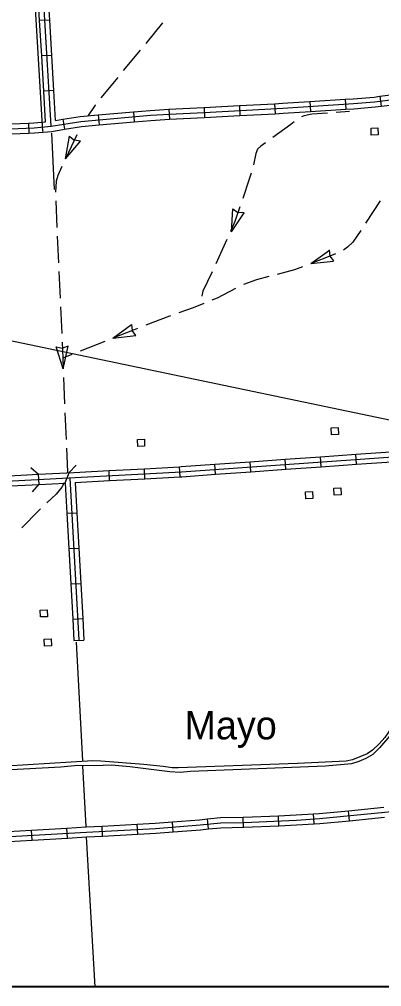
# Model space of a CAD drawing. Extents: x -0.3 to 2.65, y 0 to 1.9.
# Drawn here: x 0.8796 to 0.9445, y 0.1443 to 0.3171 of the extents above; entities that cross this region are included whole.
import ezdxf

# ---------------------------------------------------------------- set-up
doc = ezdxf.new("R2010")
doc.units = 0
for name, color, linetype in [('Default', 7, 'Continuous'), ('DSN_DRFT_DNC', 7, 'Continuous'), ('Level 11', 7, 'Continuous'), ('Level 12', 7, 'Continuous'), ('Level 14', 7, 'Continuous'), ('Level 15', 7, 'Continuous'), ('Level 19', 7, 'Continuous'), ('Level 29', 7, 'Continuous'), ('Level 6', 7, 'Continuous')]:
    doc.layers.add(name, color=color, linetype=linetype)

msp = doc.modelspace()

# ---------------------------------------------------------------- linework, layer by layer
at = {"layer": 'Default'}
msp.add_lwpolyline([(0.97177, 0.24009), (0.73293, 0.28998), (0.80083, 0.28386)], dxfattribs=at)
at = {"layer": 'DSN_DRFT_DNC'}
msp.add_lwpolyline([(0.38477, 0.54167), (1.0319, 0.54167), (1.0319, 0.1443), (0.38477, 0.1443)], close=True, dxfattribs=at)
at = {"layer": 'Level 11'}
msp.add_line((0.89162, 0.17102), (0.89316, 0.14427), dxfattribs=at)
for points in [[(0.8854, 0.29676), (0.88588, 0.2867)], [(0.88983, 0.20585), (0.89092, 0.18462)], [(0.89097, 0.18371), (0.89152, 0.17288)]]:
    msp.add_lwpolyline(points, dxfattribs=at)
at = {"layer": 'Level 12'}
for p, q in [((0.88791, 0.29222), (0.88864, 0.29627)), ((0.88864, 0.29627), (0.88948, 0.29556)), ((0.88791, 0.29222), (0.89056, 0.29536)), ((0.89056, 0.29536), (0.88949, 0.29555)), ((0.91758, 0.27914), (0.91784, 0.28324)), ((0.91758, 0.27914), (0.91986, 0.28256)), ((0.91784, 0.28324), (0.91875, 0.28263)), ((0.91986, 0.28256), (0.91876, 0.28263)), ((0.93178, 0.27348), (0.93511, 0.27588)), ((0.93507, 0.27591), (0.93521, 0.27482)), ((0.93178, 0.27348), (0.93587, 0.2739)), ((0.93588, 0.27395), (0.93522, 0.27481)), ((0.89638, 0.26015), (0.89968, 0.2626)), ((0.89968, 0.2626), (0.8998, 0.26152)), ((0.90046, 0.26063), (0.89981, 0.2615)), ((0.89638, 0.26015), (0.90046, 0.26063)), ((0.88626, 0.25862), (0.88733, 0.25838)), ((0.8875, 0.2547), (0.88626, 0.25862)), ((0.88838, 0.25871), (0.88734, 0.25838)), ((0.8875, 0.2547), (0.88838, 0.25871))]:
    msp.add_line(p, q, dxfattribs=at)
for points in [[(0.90528, 0.31649), (0.90226, 0.31283)], [(0.90126, 0.31161), (0.89824, 0.30796)], [(0.89724, 0.30674), (0.89422, 0.30308)], [(0.89322, 0.30186), (0.89318, 0.30181), (0.89196, 0.29992), (0.89194, 0.2999)], [(0.93475, 0.30038), (0.93194, 0.3002), (0.93059, 0.29989), (0.93009, 0.29968)], [(0.93869, 0.30063), (0.93632, 0.30048)], [(0.9288, 0.29879), (0.92823, 0.29831), (0.92498, 0.29599)], [(0.88993, 0.29651), (0.88791, 0.29222)], [(0.9237, 0.29508), (0.92283, 0.29445), (0.92223, 0.2939), (0.92194, 0.29312), (0.92152, 0.29114)], [(0.88724, 0.2908), (0.88651, 0.28924), (0.88624, 0.28821), (0.88611, 0.28626)], [(0.92109, 0.28962), (0.92076, 0.28858), (0.9196, 0.28513)], [(0.88615, 0.28468), (0.88637, 0.27995)], [(0.91909, 0.28363), (0.91821, 0.28101), (0.91742, 0.2792)], [(0.94417, 0.28468), (0.94158, 0.28072)], [(0.88644, 0.27837), (0.88665, 0.27364)], [(0.94071, 0.27939), (0.93932, 0.27728), (0.93837, 0.27639), (0.93762, 0.27589)], [(0.91678, 0.27776), (0.91477, 0.27346)], [(0.93619, 0.27522), (0.93427, 0.27442), (0.93178, 0.27348)], [(0.88672, 0.27206), (0.88693, 0.26732)], [(0.91411, 0.27203), (0.91247, 0.26852), (0.91227, 0.26774), (0.91227, 0.26768)], [(0.93031, 0.27292), (0.92884, 0.27236), (0.92578, 0.27155)], [(0.92425, 0.27115), (0.92207, 0.27057), (0.91972, 0.26976)], [(0.91832, 0.26903), (0.91505, 0.26731), (0.91409, 0.26692)], [(0.91262, 0.26632), (0.91071, 0.26555), (0.90818, 0.26467)], [(0.887, 0.26575), (0.88722, 0.26101)], [(0.90669, 0.26415), (0.90648, 0.26407), (0.90226, 0.26246)], [(0.90079, 0.26189), (0.90021, 0.26167), (0.89638, 0.26015)], [(0.88729, 0.25943), (0.88741, 0.25659), (0.88749, 0.2547)], [(0.89491, 0.25957), (0.89051, 0.25782)], [(0.88904, 0.25723), (0.88741, 0.25659)], [(0.88755, 0.25312), (0.88774, 0.24839)], [(0.88781, 0.24681), (0.888, 0.24207)], [(0.88806, 0.2405), (0.88823, 0.23628), (0.88821, 0.23616)], [(0.88766, 0.23428), (0.88722, 0.23351), (0.88624, 0.23226), (0.88459, 0.23071)], [(0.88344, 0.22963), (0.88306, 0.22928), (0.88009, 0.22628)]]:
    msp.add_lwpolyline(points, dxfattribs=at)
at = {"layer": 'Level 14'}
for points in [[(0.95175, 0.1989), (0.94972, 0.19527), (0.94627, 0.18952), (0.94407, 0.18692), (0.94286, 0.18578), (0.94164, 0.18505), (0.9404, 0.18451), (0.93905, 0.18411), (0.93442, 0.18368), (0.91024, 0.1827), (0.90842, 0.18252), (0.90657, 0.18267), (0.89938, 0.18355), (0.89614, 0.18384), (0.89313, 0.18374), (0.89009, 0.18382), (0.88704, 0.18352), (0.88038, 0.18311), (0.86671, 0.18245)], [(0.95178, 0.20043), (0.94566, 0.18973), (0.94505, 0.18881), (0.94403, 0.18769), (0.94284, 0.18652), (0.94185, 0.18585), (0.93925, 0.18483), (0.93808, 0.18458), (0.92938, 0.18416), (0.90804, 0.18335), (0.90699, 0.18339), (0.90537, 0.18363), (0.90194, 0.184), (0.89425, 0.18457), (0.8928, 0.18464), (0.87338, 0.18344)]]:
    msp.add_lwpolyline(points, dxfattribs=at)
at = {"layer": 'Level 15'}
for p, q in [((0.88507, 0.31699), (0.88328, 0.31689)), ((0.88545, 0.31069), (0.88365, 0.31058)), ((0.88582, 0.30438), (0.88403, 0.30427)), ((0.93791, 0.30284), (0.93803, 0.30105)), ((0.94415, 0.30338), (0.94438, 0.3016)), ((0.90638, 0.30105), (0.90648, 0.29926)), ((0.91269, 0.30135), (0.91279, 0.29956)), ((0.919, 0.3017), (0.9191, 0.29991)), ((0.92531, 0.30205), (0.92541, 0.30025)), ((0.93161, 0.30244), (0.93172, 0.30065)), ((0.88743, 0.29926), (0.88771, 0.29749)), ((0.89376, 0.30005), (0.89391, 0.29826)), ((0.90005, 0.30059), (0.90021, 0.2988)), ((0.88126, 0.29858), (0.88133, 0.29679)), ((0.93364, 0.23717), (0.93351, 0.23896)), ((0.93994, 0.23762), (0.93982, 0.23941)), ((0.90211, 0.23504), (0.90201, 0.23683)), ((0.90842, 0.23538), (0.90832, 0.23717)), ((0.91473, 0.23583), (0.91461, 0.23762)), ((0.92104, 0.23628), (0.92091, 0.23807)), ((0.92734, 0.23672), (0.92721, 0.23851)), ((0.88318, 0.23403), (0.88308, 0.23582)), ((0.88783, 0.23428), (0.88856, 0.23611)), ((0.8958, 0.2347), (0.8957, 0.2365)), ((0.88813, 0.22886), (0.88992, 0.22896)), ((0.88849, 0.22255), (0.89028, 0.22265)), ((0.88884, 0.21624), (0.89064, 0.21634)), ((0.8892, 0.20993), (0.89099, 0.21003)), ((0.88942, 0.20611), (0.89121, 0.20621)), ((0.92606, 0.17303), (0.92598, 0.17482)), ((0.93238, 0.17336), (0.93227, 0.17515)), ((0.9387, 0.17393), (0.93853, 0.17572)), ((0.89454, 0.17117), (0.89444, 0.17296)), ((0.90085, 0.17151), (0.90075, 0.1733)), ((0.90718, 0.17192), (0.90703, 0.17371)), ((0.91349, 0.17246), (0.91331, 0.17425)), ((0.91972, 0.17275), (0.91969, 0.17454)), ((0.88193, 0.17047), (0.88182, 0.17226)), ((0.88823, 0.17082), (0.88813, 0.17262))]:
    msp.add_line(p, q, dxfattribs=at)
for points in [[(0.88531, 0.29802), (0.88159, 0.36102), (0.88161, 0.36181), (0.88173, 0.36213), (0.88187, 0.36229), (0.8827, 0.36244), (0.91142, 0.36457), (0.92837, 0.36552), (0.92864, 0.36569), (0.92884, 0.36597), (0.92889, 0.36641), (0.92854, 0.37227)], [(0.88383, 0.29711), (0.88011, 0.36011), (0.88014, 0.3609), (0.88025, 0.36122), (0.88039, 0.36138), (0.88122, 0.36153), (0.90995, 0.36366), (0.92689, 0.36462), (0.92716, 0.36478), (0.92736, 0.36506), (0.92742, 0.3655), (0.92707, 0.37136)], [(0.88507, 0.31699), (0.8847, 0.3233)], [(0.88328, 0.31689), (0.88291, 0.32319)], [(0.88365, 0.31058), (0.88328, 0.31689)], [(0.88545, 0.31069), (0.88507, 0.31699)], [(0.88403, 0.30427), (0.88365, 0.31058)], [(0.88582, 0.30438), (0.88545, 0.31069)], [(0.88435, 0.29882), (0.88403, 0.30427)], [(0.88613, 0.29905), (0.88582, 0.30438)], [(0.82448, 0.29532), (0.86117, 0.29696), (0.86927, 0.29721), (0.88227, 0.29774), (0.88531, 0.29802), (0.89065, 0.29889), (0.9031, 0.29997), (0.90771, 0.30025), (0.91272, 0.30047), (0.92678, 0.30125), (0.9394, 0.30206), (0.94318, 0.30237), (0.94835, 0.30302)], [(0.93161, 0.30244), (0.93791, 0.30284)], [(0.93791, 0.30284), (0.93934, 0.30293), (0.94309, 0.30324), (0.94415, 0.30338)], [(0.94415, 0.30338), (0.94741, 0.30379)], [(0.90005, 0.30059), (0.90304, 0.30085), (0.90638, 0.30105)], [(0.90638, 0.30105), (0.90766, 0.30113), (0.91267, 0.30135), (0.91269, 0.30135)], [(0.91269, 0.30135), (0.919, 0.3017)], [(0.919, 0.3017), (0.92531, 0.30205)], [(0.92531, 0.30205), (0.92673, 0.30213), (0.93161, 0.30244)], [(0.93172, 0.30065), (0.93803, 0.30105)], [(0.93803, 0.30105), (0.93947, 0.30114), (0.94328, 0.30146), (0.94438, 0.3016)], [(0.94438, 0.3016), (0.9475, 0.30199)], [(0.88613, 0.29905), (0.88743, 0.29926)], [(0.88743, 0.29926), (0.89054, 0.29977), (0.89376, 0.30005)], [(0.89376, 0.30005), (0.90005, 0.30059)], [(0.90021, 0.2988), (0.90317, 0.29906), (0.90648, 0.29926)], [(0.90648, 0.29926), (0.90776, 0.29933), (0.91276, 0.29956), (0.91279, 0.29956)], [(0.91279, 0.29956), (0.9191, 0.29991)], [(0.9191, 0.29991), (0.92541, 0.30025)], [(0.92541, 0.30025), (0.92684, 0.30033), (0.93172, 0.30065)], [(0.87494, 0.29833), (0.88126, 0.29858)], [(0.88126, 0.29858), (0.88221, 0.29862), (0.88435, 0.29882)], [(0.88133, 0.29679), (0.88233, 0.29683), (0.88543, 0.29711), (0.88771, 0.29749)], [(0.88771, 0.29749), (0.89076, 0.29798), (0.89391, 0.29826)], [(0.89391, 0.29826), (0.90021, 0.2988)], [(0.87502, 0.29653), (0.88133, 0.29679)], [(0.82635, 0.23195), (0.85707, 0.2335), (0.90865, 0.23628), (0.94985, 0.23921)], [(0.92721, 0.23851), (0.93351, 0.23896)], [(0.93351, 0.23896), (0.93982, 0.23941)], [(0.93982, 0.23941), (0.94612, 0.23986)], [(0.8957, 0.2365), (0.90201, 0.23683)], [(0.90201, 0.23683), (0.90832, 0.23717)], [(0.90832, 0.23717), (0.9086, 0.23719), (0.91461, 0.23762)], [(0.91461, 0.23762), (0.92091, 0.23807)], [(0.92091, 0.23807), (0.92721, 0.23851)], [(0.92734, 0.23672), (0.93364, 0.23717)], [(0.93364, 0.23717), (0.93994, 0.23762)], [(0.93994, 0.23762), (0.94625, 0.23807)], [(0.87677, 0.23548), (0.88308, 0.23582)], [(0.88308, 0.23582), (0.88939, 0.23616)], [(0.88866, 0.23521), (0.89029, 0.20618)], [(0.88939, 0.23616), (0.8957, 0.2365)], [(0.90211, 0.23504), (0.90842, 0.23538)], [(0.90842, 0.23538), (0.90871, 0.2354), (0.91473, 0.23583)], [(0.91473, 0.23583), (0.92104, 0.23628)], [(0.92104, 0.23628), (0.92734, 0.23672)], [(0.87687, 0.23369), (0.88318, 0.23403)], [(0.88318, 0.23403), (0.88783, 0.23427)], [(0.88783, 0.23427), (0.88813, 0.22886)], [(0.88962, 0.23437), (0.8958, 0.2347)], [(0.88962, 0.23437), (0.88992, 0.22896)], [(0.8958, 0.2347), (0.90211, 0.23504)], [(0.88813, 0.22886), (0.88849, 0.22255)], [(0.88992, 0.22896), (0.89028, 0.22265)], [(0.88849, 0.22255), (0.88884, 0.21624)], [(0.89028, 0.22265), (0.89064, 0.21634)], [(0.88884, 0.21624), (0.8892, 0.20993)], [(0.89064, 0.21634), (0.89099, 0.21003)], [(0.8892, 0.20993), (0.88942, 0.20611)], [(0.89099, 0.21003), (0.89121, 0.20621)], [(0.93853, 0.17572), (0.94482, 0.17633)], [(0.79986, 0.16752), (0.81517, 0.16826), (0.81961, 0.16841), (0.82139, 0.16854), (0.82399, 0.16832), (0.83746, 0.16916), (0.8589, 0.17005), (0.89163, 0.1719), (0.90402, 0.17256), (0.91199, 0.17319), (0.91566, 0.17356), (0.91979, 0.17363), (0.9292, 0.17405), (0.93334, 0.1743), (0.95299, 0.1762)], [(0.91969, 0.17454), (0.91976, 0.17454), (0.92598, 0.17482)], [(0.92598, 0.17482), (0.92916, 0.17497), (0.93227, 0.17515)], [(0.93227, 0.17515), (0.93326, 0.17521), (0.93853, 0.17572)], [(0.88813, 0.17262), (0.89158, 0.17281), (0.89444, 0.17296)], [(0.89444, 0.17296), (0.90075, 0.1733)], [(0.90075, 0.1733), (0.90396, 0.17347), (0.90703, 0.17371)], [(0.90703, 0.17371), (0.9119, 0.1741), (0.91331, 0.17425)], [(0.91331, 0.17425), (0.91561, 0.17448), (0.91969, 0.17454)], [(0.91972, 0.17275), (0.91981, 0.17275), (0.92606, 0.17303)], [(0.92606, 0.17303), (0.92925, 0.17317), (0.93238, 0.17336)], [(0.93238, 0.17336), (0.9334, 0.17342), (0.9387, 0.17393)], [(0.9387, 0.17393), (0.94499, 0.17454)], [(0.87552, 0.1719), (0.88182, 0.17226)], [(0.88182, 0.17226), (0.88813, 0.17262)], [(0.88823, 0.17082), (0.89168, 0.17102), (0.89454, 0.17117)], [(0.89454, 0.17117), (0.90085, 0.17151)], [(0.90085, 0.17151), (0.90408, 0.17168), (0.90718, 0.17192)], [(0.90718, 0.17192), (0.91207, 0.17232), (0.91349, 0.17246)], [(0.91349, 0.17246), (0.91571, 0.17268), (0.91972, 0.17275)], [(0.87562, 0.17011), (0.88193, 0.17047)], [(0.88193, 0.17047), (0.88823, 0.17082)]]:
    msp.add_lwpolyline(points, dxfattribs=at)
at = {"layer": 'Level 19'}
for points in [[(0.9426, 0.29643), (0.94255, 0.29767), (0.94379, 0.29773), (0.94385, 0.29648)], [(0.93547, 0.2429), (0.93542, 0.24415), (0.93667, 0.2442), (0.93672, 0.24296)], [(0.90082, 0.24081), (0.90076, 0.24205), (0.90201, 0.24211), (0.90206, 0.24086)], [(0.93596, 0.23209), (0.93591, 0.23333), (0.93716, 0.23338), (0.93721, 0.23214)], [(0.93088, 0.23145), (0.93082, 0.2327), (0.93207, 0.23275), (0.93213, 0.23151)], [(0.88345, 0.21033), (0.88339, 0.21157), (0.88464, 0.21163), (0.88469, 0.21038)], [(0.88414, 0.20512), (0.88409, 0.20637), (0.88534, 0.20642), (0.88539, 0.20518)]]:
    msp.add_lwpolyline(points, close=True, dxfattribs=at)
at = {"layer": 'Level 29'}
for points in [[(0.88172, 0.23705), (0.88305, 0.23585)], [(0.88858, 0.23612), (0.88978, 0.23745)], [(0.88315, 0.23405), (0.88195, 0.23272)]]:
    msp.add_lwpolyline(points, dxfattribs=at)
at = {"layer": 'Level 6'}
msp.add_line((0.38476, 0.14427), (1.03189, 0.14427), dxfattribs=at)

# ---------------------------------------------------------------- texts
at = {"layer": 'Level 14'}
msp.add_text('Mayo', height=0.005055, dxfattribs=at).set_placement((0.90917, 0.18846))

doc.saveas('drawing.dxf')
